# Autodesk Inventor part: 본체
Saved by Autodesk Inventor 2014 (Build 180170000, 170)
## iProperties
Created: 2026-08
Part Number: 본체
Material: 일반
Document SubType Name: Modeling
Designer: dg
Density: 1 g/cm^3
Appearance: 기본값
Author: dg
Author: jhkim
Creation Date: 2026-07-31
Sending System: Autodesk Inventor 2027
Preprocessor: ST-DEVELOPER v20.1
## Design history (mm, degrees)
node "본체1"
node "솔리드1"
node "기준1"
